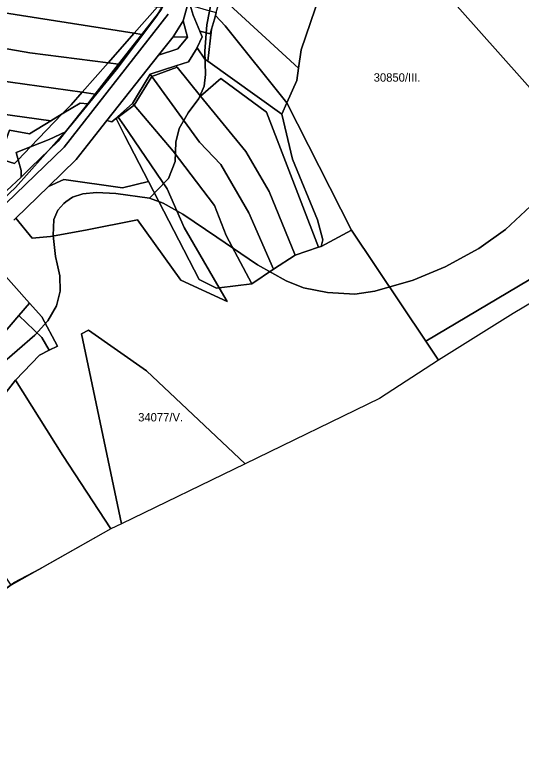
# Model space of a CAD drawing. Extents: x -535894 to -532834, y -1165802 to -1163645.
# Drawn here: x -533943.2 to -533641.6, y -1165382.2 to -1164945 of the extents above; entities that cross this region are included whole.
import ezdxf

# ---------------------------------------------------------------- set-up
doc = ezdxf.new("R2010")
doc.units = 0
for name, color, linetype in [('95560013', 7, 'Continuous'), ('95590013', 7, 'Continuous'), ('95600013', 7, 'Continuous'), ('95610013', 7, 'Continuous'), ('95630013', 7, 'Continuous'), ('95640013', 7, 'Continuous'), ('95660013', 7, 'Continuous')]:
    doc.layers.add(name, color=color, linetype=linetype)

msp = doc.modelspace()

# ---------------------------------------------------------------- linework, layer by layer
at = {"layer": '95560013'}
msp.add_lwpolyline([(-533742.52, -1164866.61), (-533736.23, -1164866.01), (-533737.9, -1164874.36), (-533755.71, -1164908.94), (-533761.58, -1164933.18), (-533772.59, -1164965.85), (-533774.28, -1164976.84), (-533820.25, -1164934.38), (-533804.16, -1164898.7), (-533796.49, -1164887.05), (-533776.21, -1164876.21), (-533758.34, -1164877.03)], close=True, dxfattribs=at)
at = {"layer": '95590013'}
for points in [[(-533755.71, -1164908.94), (-533737.9, -1164874.36), (-533570, -1165063.27), (-533698.37, -1165139.6), (-533742.77, -1165073.32), (-533781.22, -1164997.48), (-533775.32, -1164984.22), (-533774.28, -1164976.84), (-533772.59, -1164965.85), (-533761.58, -1164933.18)], [(-533821.32, -1164936.75), (-533820.25, -1164934.38), (-533774.28, -1164976.84), (-533775.32, -1164984.22), (-533781.22, -1164997.48), (-533817.86, -1164951.61), (-533823.73, -1164945.5), (-533823.23, -1164943.69)], [(-533824.3, -1164947.57), (-533823.73, -1164945.5), (-533817.86, -1164951.61), (-533781.22, -1164997.48), (-533784.18, -1165004.34), (-533828.25, -1164972.65), (-533825.98, -1164953.67)], [(-533833.05, -1164954.72), (-533831.37, -1164955.18), (-533826.74, -1164956.45), (-533825.98, -1164953.67), (-533828.25, -1164972.65), (-533830.03, -1164971.49), (-533834.67, -1164964.81), (-533834.53, -1164964.59), (-533831.57, -1164958.17)], [(-533834.67, -1164964.81), (-533830.03, -1164971.49), (-533828.25, -1164972.65), (-533784.18, -1165004.34), (-533777.91, -1165031.04), (-533762.95, -1165067.3), (-533759.69, -1165079.1), (-533760.78, -1165083.11), (-533762.32, -1165083.63), (-533793.32, -1165003.01), (-533820.39, -1164982.94), (-533832.53, -1164993.45), (-533846.51, -1164976.33), (-533847.23, -1164975.45), (-533839.81, -1164972.99)], [(-533570, -1165063.27), (-533561.52, -1165072.67), (-533646.35, -1165122.98), (-533690.81, -1165150.82), (-533698.37, -1165139.6)]]:
    msp.add_lwpolyline(points, close=True, dxfattribs=at)
at = {"layer": '95600013'}
msp.add_lwpolyline([(-533570, -1165063.27), (-533737.9, -1164874.36), (-533736.23, -1164866.01), (-533724, -1164860.16), (-533717.48, -1164860.13), (-533696.31, -1164848.54), (-533670.19, -1164839.35), (-533626.96, -1164831.3)], dxfattribs=at)
at = {"layer": '95610013'}
for points in [[(-533846.51, -1164976.33), (-533861.56, -1164981.81), (-533862.51, -1164980.51), (-533847.23, -1164975.45)], [(-533861.56, -1164981.81), (-533846.51, -1164976.33), (-533832.53, -1164993.45), (-533805.59, -1165026.46), (-533791.78, -1165050.33), (-533776.32, -1165088.28), (-533789.06, -1165096.75), (-533803.83, -1165063.03), (-533820.54, -1165034.21), (-533833.13, -1165020.87)], [(-533862.51, -1164980.51), (-533861.56, -1164981.81), (-533872.11, -1164998.92), (-533873, -1164997.87)], [(-533872.11, -1164998.92), (-533861.56, -1164981.81), (-533833.13, -1165020.87), (-533820.54, -1165034.21), (-533803.83, -1165063.03), (-533789.06, -1165096.75), (-533801.99, -1165105.35), (-533817.35, -1165076.54), (-533824.2, -1165058.65), (-533848.91, -1165026.4)], [(-533820.39, -1164982.94), (-533793.32, -1165003.01), (-533762.32, -1165083.63), (-533776.32, -1165088.28), (-533791.78, -1165050.33), (-533805.59, -1165026.46), (-533832.53, -1164993.45)], [(-533872.11, -1164998.92), (-533881.57, -1165005.98), (-533881.73, -1165005.74), (-533873, -1164997.87)], [(-533881.57, -1165005.98), (-533872.11, -1164998.92), (-533848.91, -1165026.4), (-533824.2, -1165058.65), (-533817.35, -1165076.54), (-533801.99, -1165105.35), (-533821.44, -1165107.85), (-533842.3, -1165071.83), (-533852.39, -1165048.84), (-533878.27, -1165010.84)], [(-533784.18, -1165004.34), (-533781.22, -1164997.48), (-533742.77, -1165073.32), (-533760.78, -1165083.11), (-533759.69, -1165079.1), (-533762.95, -1165067.3), (-533777.91, -1165031.04)], [(-533962.53, -1165085.32), (-533934.45, -1165116.87), (-533940.8, -1165124.3), (-534005.15, -1165199.61), (-534012.92, -1165190.05), (-534014.17, -1165173.12), (-534019.14, -1165162.52), (-534024.54, -1165159.35), (-534021.42, -1165157.14), (-534022.96, -1165151.54), (-534010.91, -1165138.64), (-533976.02, -1165098.2)], [(-533940.8, -1165124.3), (-533934.45, -1165116.87), (-533927.15, -1165125.06), (-533917.7, -1165142.45), (-533922.67, -1165144.99), (-533927.13, -1165137.47)], [(-533940.8, -1165124.3), (-533927.13, -1165137.47), (-533922.67, -1165144.99), (-533928.42, -1165147.92), (-533942.82, -1165162.9), (-533962.19, -1165187.57), (-533989.71, -1165212.03), (-534005.15, -1165199.61)], [(-533903.4, -1165135.17), (-533899.27, -1165133.08), (-533864.82, -1165157.28), (-533806.07, -1165212.59), (-533879.59, -1165248.35)], [(-533962.19, -1165187.57), (-533942.82, -1165162.9), (-533914.6, -1165207.64), (-533885.93, -1165251.42), (-533945.33, -1165285.03), (-533992.77, -1165214.76), (-533989.71, -1165212.03)]]:
    msp.add_lwpolyline(points, close=True, dxfattribs=at)
msp.add_lwpolyline([(-533943.82, -1165067.47), (-533942.64, -1165066.34), (-533932.89, -1165078.2), (-533921.87, -1165077.16), (-533901.06, -1165073.37), (-533870.09, -1165067.22), (-533844.4, -1165103.16), (-533816.78, -1165115.9), (-533821.44, -1165107.85), (-533801.99, -1165105.35), (-533789.06, -1165096.75), (-533776.32, -1165088.28), (-533762.32, -1165083.63), (-533760.78, -1165083.11), (-533742.77, -1165073.32), (-533698.37, -1165139.6), (-533690.81, -1165150.82), (-533726.09, -1165173.68), (-533806.07, -1165212.59), (-533864.82, -1165157.28), (-533899.27, -1165133.08), (-533903.4, -1165135.17), (-533879.59, -1165248.35), (-533885.93, -1165251.42), (-533914.6, -1165207.64), (-533942.82, -1165162.9), (-533928.42, -1165147.92), (-533922.67, -1165144.99), (-533917.7, -1165142.45), (-533927.15, -1165125.06), (-533934.45, -1165116.87), (-533962.53, -1165085.32)], dxfattribs=at)
at = {"layer": '95630013'}
for points in [[(-533840.25, -1164939.22), (-533842.95, -1164948.65), (-533848.9, -1164958.14), (-533857.58, -1164969.11), (-533888.41, -1165008.1), (-533902.3, -1165025.67), (-533906.69, -1165031.23), (-533923.15, -1165047.3), (-533942.64, -1165066.34), (-533943.82, -1165067.47)], [(-533971.79, -1165079.79), (-533913.79, -1165024.04), (-533851.83, -1164944.65)]]:
    msp.add_lwpolyline(points, dxfattribs=at)
at = {"layer": '95640013'}
for points in [[(-533932.96, -1164927.87), (-533906.44, -1164932.7), (-533893.29, -1164935.49), (-533882.11, -1164937.86), (-533879.19, -1164938.15), (-533865.26, -1164939.55), (-533858.16, -1164940.26), (-533872.1, -1164956.08), (-533949.39, -1164943.93), (-533957.74, -1164942.58), (-533951.96, -1164924.41)], [(-534012.88, -1164933.73), (-534002.31, -1164935.43), (-534002.59, -1164936.19), (-533995.11, -1164939.02), (-533994.24, -1164936.72), (-533968.93, -1164940.8), (-533970.51, -1164945.79), (-533967.85, -1164946.68), (-533968.66, -1164949.26), (-533963.29, -1164950.96), (-533962.47, -1164948.39), (-533959.85, -1164949.22), (-533957.74, -1164942.58), (-533949.39, -1164943.93), (-533872.1, -1164956.08), (-533887.6, -1164973.66), (-533934.25, -1164967.65), (-533986.88, -1164958.63), (-534018.61, -1164950.58)], [(-533840.25, -1164939.22), (-533839.74, -1164936.26), (-533838.84, -1164939.32), (-533837.05, -1164945.36), (-533833.05, -1164954.72), (-533831.57, -1164958.17), (-533834.53, -1164964.59), (-533834.67, -1164964.81), (-533839.81, -1164972.99), (-533847.23, -1164975.45), (-533862.51, -1164980.51), (-533873, -1164997.87), (-533881.73, -1165005.74), (-533882.92, -1165006.8), (-533885.29, -1165008.94), (-533888.41, -1165008.1), (-533857.58, -1164969.11), (-533846.11, -1164965.37), (-533840.3, -1164958.31), (-533842.95, -1164948.65)], [(-533855.19, -1164940.56), (-533856.28, -1164942.38), (-533867.55, -1164956.8), (-533872.1, -1164956.08), (-533858.16, -1164940.26)], [(-533838.84, -1164939.32), (-533831.21, -1164941.49), (-533830.64, -1164941.66), (-533823.23, -1164943.69), (-533823.73, -1164945.5), (-533824.3, -1164947.57), (-533825.98, -1164953.67), (-533826.74, -1164956.45), (-533831.37, -1164955.18), (-533833.05, -1164954.72), (-533837.05, -1164945.36)], [(-534018.61, -1164950.58), (-533986.88, -1164958.63), (-533934.25, -1164967.65), (-533887.6, -1164973.66), (-533903.09, -1164991.22), (-533954.36, -1164984.01), (-534025.02, -1164969.45)], [(-533842.95, -1164948.65), (-533840.3, -1164958.31), (-533848.9, -1164958.14)], [(-533872.1, -1164956.08), (-533867.55, -1164956.8), (-533881.35, -1164974.47), (-533887.6, -1164973.66)], [(-533848.9, -1164958.14), (-533840.3, -1164958.31), (-533846.11, -1164965.37), (-533857.58, -1164969.11)], [(-533982.32, -1164978.93), (-533988.74, -1164997.2), (-534031.7, -1164989.14), (-534025.02, -1164969.45), (-533954.36, -1164984.01), (-533903.09, -1164991.22), (-533909.61, -1164998.62), (-533914.87, -1165004.11), (-533921.79, -1165008.29), (-533953.32, -1165003.84), (-533979.75, -1164998.88), (-533973.77, -1164981.91)], [(-533887.6, -1164973.66), (-533881.35, -1164974.47), (-533895.29, -1164992.32), (-533903.09, -1164991.22)], [(-534031.7, -1164989.14), (-533988.74, -1164997.2), (-533992.43, -1165007.68), (-533983.9, -1165010.68), (-533979.75, -1164998.88), (-533953.32, -1165003.84), (-533921.79, -1165008.29), (-533934.5, -1165015.99), (-533946.24, -1165013.85), (-533950.91, -1165026.24), (-533995.12, -1165018), (-534028.02, -1165008.03), (-534034.52, -1164997.43)], [(-533903.09, -1164991.22), (-533895.29, -1164992.32), (-533899.75, -1164998.03), (-533904.3, -1164997.71), (-533914.87, -1165004.11), (-533909.61, -1164998.62)], [(-533904.3, -1164997.71), (-533899.75, -1164998.03), (-533912.91, -1165014.89), (-533922.74, -1165019.41), (-533933.76, -1165023.78), (-533914.87, -1165004.11)], [(-533921.79, -1165008.29), (-533914.87, -1165004.11), (-533933.76, -1165023.78), (-533942.33, -1165027.2), (-533941.12, -1165031.45), (-533943.27, -1165033.69), (-533950.22, -1165031.59), (-533950.91, -1165026.24), (-533946.24, -1165013.85), (-533934.5, -1165015.99)], [(-533882.92, -1165006.8), (-533882.85, -1165006.93), (-533877.59, -1165017.13), (-533863.57, -1165044.37), (-533879.05, -1165048.19), (-533913.9, -1165043.12), (-533923.15, -1165047.3), (-533906.69, -1165031.23), (-533902.3, -1165025.67), (-533888.41, -1165008.1), (-533885.29, -1165008.94)], [(-533881.57, -1165005.98), (-533882.85, -1165006.93), (-533882.92, -1165006.8), (-533881.73, -1165005.74)], [(-533882.85, -1165006.93), (-533881.57, -1165005.98), (-533878.27, -1165010.84), (-533852.39, -1165048.84), (-533842.3, -1165071.83), (-533821.44, -1165107.85), (-533823.1, -1165108.06), (-533833.46, -1165102.84), (-533863.57, -1165044.37), (-533877.59, -1165017.13)], [(-533922.74, -1165019.41), (-533912.91, -1165014.89), (-533917.25, -1165020.44), (-533933.4, -1165035.94), (-533939.43, -1165041.74), (-533939.32, -1165037.78), (-533941.12, -1165031.45), (-533933.76, -1165023.78)], [(-533942.33, -1165027.2), (-533933.76, -1165023.78), (-533941.12, -1165031.45)], [(-533943.27, -1165033.69), (-533941.12, -1165031.45), (-533939.32, -1165037.78), (-533939.43, -1165041.74), (-533947.86, -1165049.82), (-533950.22, -1165031.59)], [(-533923.15, -1165047.3), (-533913.9, -1165043.12), (-533879.05, -1165048.19), (-533863.57, -1165044.37), (-533833.46, -1165102.84), (-533823.1, -1165108.06), (-533821.44, -1165107.85), (-533816.78, -1165115.9), (-533844.4, -1165103.16), (-533870.09, -1165067.22), (-533901.06, -1165073.37), (-533921.87, -1165077.16), (-533932.89, -1165078.2), (-533942.64, -1165066.34)]]:
    msp.add_lwpolyline(points, close=True, dxfattribs=at)
for points in [[(-533947.86, -1165049.82), (-533939.43, -1165041.74), (-533933.4, -1165035.94), (-533917.25, -1165020.44), (-533912.91, -1165014.89), (-533899.75, -1164998.03), (-533895.29, -1164992.32), (-533881.35, -1164974.47), (-533867.55, -1164956.8), (-533856.28, -1164942.38)], [(-533851.83, -1164944.65), (-533913.79, -1165024.04), (-533971.79, -1165079.79)]]:
    msp.add_lwpolyline(points, dxfattribs=at)
at = {"layer": '95660013'}
for points in [[(-533840.52, -1164915.19), (-533858.68, -1164945.769), (-533882.731, -1164977.94), (-533910.29, -1165011.39), (-533942.78, -1165048.02), (-533990.56, -1165093.1)], [(-533990.56, -1165093.1), (-533942.78, -1165048.02), (-533910.29, -1165011.39), (-533882.731, -1164977.94), (-533858.68, -1164945.769), (-533840.52, -1164915.19)], [(-533825.793, -1164935.576), (-533828.81, -1164951.02), (-533830.01, -1164966.71), (-533829.69, -1164980.571), (-533830.33, -1164987.66), (-533833.576, -1164994.919), (-533839.96, -1165003.51), (-533845.38, -1165012.74), (-533847.255, -1165021.032), (-533847.61, -1165032.5), (-533851.59, -1165042.53), (-533852.7, -1165043.679), (-533862.9, -1165054.24), (-533883.051, -1165051.61), (-533894.52, -1165050.89), (-533902.587, -1165051.673), (-533908.77, -1165053.681), (-533912.759, -1165056.577), (-533914.03, -1165057.5), (-533917.61, -1165061.48), (-533920, -1165067.14), (-533920.4, -1165076.62), (-533918.89, -1165089.12), (-533917.922, -1165093.478), (-533916.35, -1165100.556), (-533916.1, -1165109.67), (-533918.33, -1165118.51), (-533923.51, -1165127.35), (-533931.15, -1165135.95), (-533952.57, -1165154.34)], [(-533636.09, -1165059.169), (-533650.981, -1165073.11), (-533666.909, -1165084.26), (-533686.98, -1165095.33), (-533706.01, -1165103.14), (-533728.87, -1165109.75), (-533740.73, -1165111.5), (-533757.06, -1165110.541), (-533771.32, -1165107.75), (-533781.59, -1165103.61), (-533798.699, -1165094), (-533822.84, -1165077.65), (-533843.07, -1165063.95), (-533854.78, -1165057.34), (-533862.9, -1165054.24), (-533852.7, -1165043.679), (-533851.59, -1165042.53), (-533847.61, -1165032.5), (-533847.255, -1165021.032), (-533845.38, -1165012.74), (-533839.96, -1165003.51), (-533833.576, -1164994.919), (-533830.33, -1164987.66), (-533829.69, -1164980.571), (-533830.01, -1164966.71), (-533828.81, -1164951.02), (-533825.793, -1164935.576)], [(-533952.57, -1165154.34), (-533931.15, -1165135.95), (-533923.51, -1165127.35), (-533918.33, -1165118.51), (-533916.1, -1165109.67), (-533916.35, -1165100.556), (-533917.922, -1165093.478), (-533918.89, -1165089.12), (-533920.4, -1165076.62), (-533920, -1165067.14), (-533917.61, -1165061.48), (-533914.03, -1165057.5), (-533912.759, -1165056.577), (-533908.77, -1165053.681), (-533902.587, -1165051.673), (-533894.52, -1165050.89), (-533883.051, -1165051.61), (-533862.9, -1165054.24), (-533854.78, -1165057.34), (-533843.07, -1165063.95), (-533822.84, -1165077.65), (-533798.699, -1165094), (-533781.59, -1165103.61), (-533771.32, -1165107.75), (-533757.06, -1165110.541), (-533740.73, -1165111.5), (-533728.87, -1165109.75), (-533706.01, -1165103.14), (-533686.98, -1165095.33), (-533666.909, -1165084.26), (-533650.981, -1165073.11), (-533636.09, -1165059.169)], [(-533561.52, -1165072.67), (-533646.35, -1165122.98), (-533690.81, -1165150.82), (-533726.09, -1165173.68), (-533806.07, -1165212.59), (-533879.59, -1165248.35), (-533885.93, -1165251.42), (-533928.089, -1165275.274), (-533943.99, -1165283.5)]]:
    msp.add_lwpolyline(points, dxfattribs=at)
msp.add_lwpolyline([(-534075.22, -1165379.41), (-534079.092, -1165382.22), (-534013.02, -1165333.89), (-533974.66, -1165305.36), (-533943.99, -1165283.5), (-533928.089, -1165275.274), (-533945.33, -1165285.03), (-533972.2, -1165304.55), (-533978.9, -1165309.42), (-533984.1, -1165313.19), (-533990.15, -1165317.59), (-533996.63, -1165322.3), (-534003.61, -1165327.37), (-534009.54, -1165331.68), (-534014.32, -1165335.17), (-534019.31, -1165338.8), (-534026.18, -1165343.78), (-534031.82, -1165347.88), (-534037.71, -1165352.16), (-534044.14, -1165356.83), (-534052.73, -1165363.08), (-534059.04, -1165367.66), (-534067.65, -1165373.91)], close=True, dxfattribs=at)

# ---------------------------------------------------------------- texts
for s, rotation, p in [('30850/III.', 0, (-533729.465, -1164984.907)), ('34077/V.', 360, (-533869.713, -1165187.4))]:
    msp.add_text(s, height=5, rotation=rotation, dxfattribs=at).set_placement(p)

doc.saveas('drawing.dxf')
